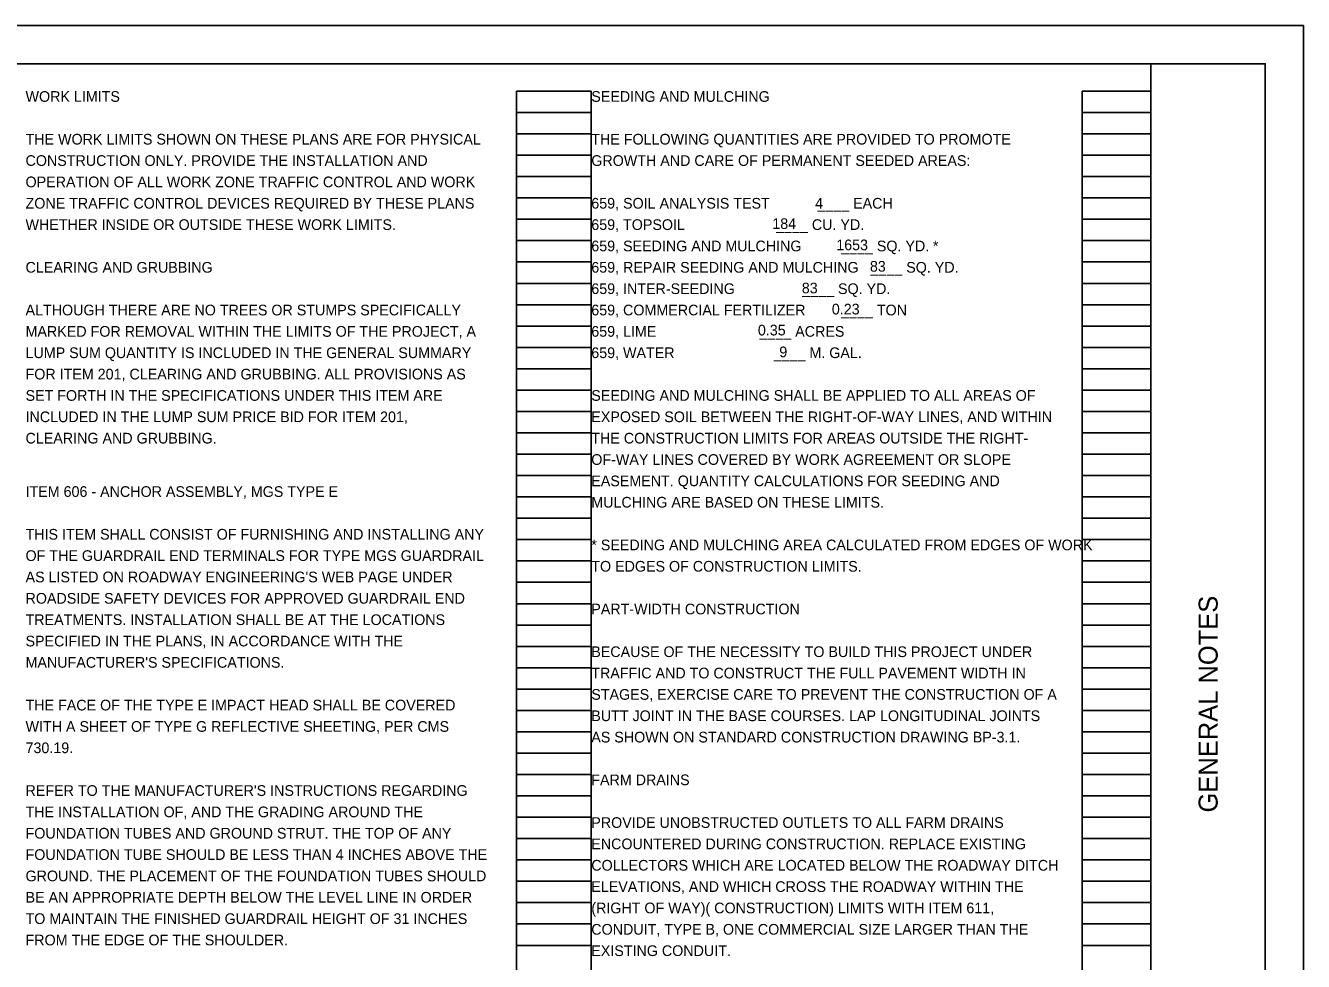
# Model space of a CAD drawing. Extents: x 0 to 37.9, y 0 to 22.
# Drawn here: x 17.24 to 34, y 9.73 to 22 of the extents above; entities that cross this region are included whole.
import ezdxf

# ---------------------------------------------------------------- set-up
doc = ezdxf.new("R2010")
doc.units = 0
for name, color, linetype in [('SH_Border', 7, 'Continuous'), ('SH_Cut_Line', 7, 'Continuous'), ('SH_Data', 7, 'Continuous'), ('SH_Text', 7, 'Continuous')]:
    doc.layers.add(name, color=color, linetype=linetype)

msp = doc.modelspace()

# ---------------------------------------------------------------- linework, layer by layer
at = {"layer": 'SH_Border'}
msp.add_line((32, 0.5), (32, 21.5), dxfattribs=at)
msp.add_lwpolyline([(1.5, 21.5), (33.5, 21.5), (33.5, 0.5), (1.5, 0.5)], close=True, dxfattribs=at)
at = {"layer": 'SH_Cut_Line'}
msp.add_lwpolyline([(0, 0), (34, 0), (34, 22), (0, 22)], close=True, dxfattribs=at)
at = {"layer": 'SH_Data'}
for p, q in [((23.68, 0.98), (23.68, 21.14)), ((23.68, 21.14), (24.66, 21.14)), ((24.66, 0.98), (24.66, 21.14)), ((31.1, 0.98), (31.1, 21.14)), ((31.1, 21.14), (32, 21.14)), ((32, 0.98), (32, 21.14)), ((23.68, 20.86), (24.66, 20.86)), ((31.1, 20.86), (32, 20.86)), ((23.68, 20.58), (24.66, 20.58)), ((31.1, 20.58), (32, 20.58)), ((23.68, 20.3), (24.66, 20.3)), ((31.1, 20.3), (32, 20.3)), ((23.68, 20.02), (24.66, 20.02)), ((31.1, 20.02), (32, 20.02)), ((23.68, 19.74), (24.66, 19.74)), ((31.1, 19.74), (32, 19.74)), ((23.68, 19.46), (24.66, 19.46)), ((31.1, 19.46), (32, 19.46)), ((23.68, 19.18), (24.66, 19.18)), ((31.1, 19.18), (32, 19.18)), ((23.68, 18.9), (24.66, 18.9)), ((31.1, 18.9), (32, 18.9)), ((23.68, 18.62), (24.66, 18.62)), ((31.1, 18.62), (32, 18.62)), ((23.68, 18.34), (24.66, 18.34)), ((31.1, 18.34), (32, 18.34)), ((23.68, 18.06), (24.66, 18.06)), ((31.1, 18.06), (32, 18.06)), ((23.68, 17.78), (24.66, 17.78)), ((31.1, 17.78), (32, 17.78)), ((23.68, 17.5), (24.66, 17.5)), ((31.1, 17.5), (32, 17.5)), ((23.68, 17.22), (24.66, 17.22)), ((31.1, 17.22), (32, 17.22)), ((23.68, 16.94), (24.66, 16.94)), ((31.1, 16.94), (32, 16.94)), ((23.68, 16.66), (24.66, 16.66)), ((31.1, 16.66), (32, 16.66)), ((23.68, 16.38), (24.66, 16.38)), ((31.1, 16.38), (32, 16.38)), ((23.68, 16.1), (24.66, 16.1)), ((31.1, 16.1), (32, 16.1)), ((23.68, 15.82), (24.66, 15.82)), ((31.1, 15.82), (32, 15.82)), ((23.68, 15.54), (24.66, 15.54)), ((31.1, 15.54), (32, 15.54)), ((23.68, 15.26), (24.66, 15.26)), ((31.1, 15.26), (32, 15.26)), ((23.68, 14.98), (24.66, 14.98)), ((31.1, 14.98), (32, 14.98)), ((23.68, 14.7), (24.66, 14.7)), ((31.1, 14.7), (32, 14.7)), ((23.68, 14.42), (24.66, 14.42)), ((31.1, 14.42), (32, 14.42)), ((23.68, 14.14), (24.66, 14.14)), ((31.1, 14.14), (32, 14.14)), ((23.68, 13.86), (24.66, 13.86)), ((31.1, 13.86), (32, 13.86)), ((23.68, 13.58), (24.66, 13.58)), ((31.1, 13.58), (32, 13.58)), ((23.68, 13.3), (24.66, 13.3)), ((31.1, 13.3), (32, 13.3)), ((23.68, 13.02), (24.66, 13.02)), ((31.1, 13.02), (32, 13.02)), ((23.68, 12.74), (24.66, 12.74)), ((31.1, 12.74), (32, 12.74)), ((23.68, 12.46), (24.66, 12.46)), ((31.1, 12.46), (32, 12.46)), ((23.68, 12.18), (24.66, 12.18)), ((31.1, 12.18), (32, 12.18)), ((23.68, 11.9), (24.66, 11.9)), ((31.1, 11.9), (32, 11.9)), ((23.68, 11.62), (24.66, 11.62)), ((31.1, 11.62), (32, 11.62)), ((23.68, 11.34), (24.66, 11.34)), ((31.1, 11.34), (32, 11.34)), ((23.68, 11.06), (24.66, 11.06)), ((31.1, 11.06), (32, 11.06)), ((23.68, 10.78), (24.66, 10.78)), ((31.1, 10.78), (32, 10.78)), ((23.68, 10.5), (24.66, 10.5)), ((31.1, 10.5), (32, 10.5)), ((23.68, 10.22), (24.66, 10.22)), ((31.1, 10.22), (32, 10.22)), ((23.68, 9.94), (24.66, 9.94)), ((31.1, 9.94), (32, 9.94))]:
    msp.add_line(p, q, dxfattribs=at)

# ---------------------------------------------------------------- texts
msp.add_text('GENERAL NOTES', height=0.25, rotation=90, dxfattribs=at).set_placement((32.875, 11.682))
at = {"layer": 'SH_Text'}
for s, p in [('WORK LIMITS', (17.24, 21)), ('SEEDING AND MULCHING', (24.66, 21)), ('THE WORK LIMITS SHOWN ON THESE PLANS ARE FOR PHYSICAL', (17.24, 20.44)), ('THE FOLLOWING QUANTITIES ARE PROVIDED TO PROMOTE', (24.66, 20.44)), ('CONSTRUCTION ONLY. PROVIDE THE INSTALLATION AND', (17.24, 20.16)), ('GROWTH AND CARE OF PERMANENT SEEDED AREAS:', (24.66, 20.16)), ('OPERATION OF ALL WORK ZONE TRAFFIC CONTROL AND WORK', (17.24, 19.88)), ('ZONE TRAFFIC CONTROL DEVICES REQUIRED BY THESE PLANS', (17.24, 19.6)), ('659, SOIL ANALYSIS TEST            ____ EACH', (24.66, 19.6)), ('4', (27.595, 19.6)), ('WHETHER INSIDE OR OUTSIDE THESE WORK LIMITS.', (17.24, 19.32)), ('659, TOPSOIL                       ____ CU. YD.', (24.66, 19.32)), ('184', (27.034, 19.333)), ('659, SEEDING AND MULCHING          ____ SQ. YD.', (24.66, 19.04)), ('1653', (27.873, 19.054)), ('*', (29.14, 19.04)), ('CLEARING AND GRUBBING', (17.24, 18.76)), ('659, REPAIR SEEDING AND MULCHING   ____ SQ. YD.', (24.66, 18.76)), ('83', (28.314, 18.773)), ('659, INTER-SEEDING                 ____ SQ. YD.', (24.66, 18.48)), ('83', (27.421, 18.489)), ('ALTHOUGH THERE ARE NO TREES OR STUMPS SPECIFICALLY', (17.24, 18.2)), ('659, COMMERCIAL FERTILIZER         ____ TON', (24.66, 18.2)), ('0.23', (27.815, 18.212)), ('MARKED FOR REMOVAL WITHIN THE LIMITS OF THE PROJECT, A', (17.24, 17.92)), ('659, LIME                          ____ ACRES', (24.66, 17.92)), ('0.35', (26.845, 17.937)), ('LUMP SUM QUANTITY IS INCLUDED IN THE GENERAL SUMMARY', (17.24, 17.64)), ('659, WATER                         ____ M. GAL.', (24.66, 17.64)), ('9', (27.126, 17.651)), ('FOR ITEM 201, CLEARING AND GRUBBING. ALL PROVISIONS AS', (17.24, 17.36)), ('SET FORTH IN THE SPECIFICATIONS UNDER THIS ITEM ARE', (17.24, 17.08)), ('SEEDING AND MULCHING SHALL BE APPLIED TO ALL AREAS OF', (24.66, 17.08)), ('INCLUDED IN THE LUMP SUM PRICE BID FOR ITEM 201,', (17.24, 16.8)), ('EXPOSED SOIL BETWEEN THE RIGHT-OF-WAY LINES, AND WITHIN', (24.66, 16.8)), ('CLEARING AND GRUBBING.', (17.24, 16.52)), ('THE CONSTRUCTION LIMITS FOR AREAS OUTSIDE THE RIGHT-', (24.66, 16.52)), ('OF-WAY LINES COVERED BY WORK AGREEMENT OR SLOPE', (24.66, 16.24)), ('EASEMENT. QUANTITY CALCULATIONS FOR SEEDING AND', (24.66, 15.96)), ('ITEM 606 - ANCHOR ASSEMBLY, MGS TYPE E', (17.24, 15.82)), ('MULCHING ARE BASED ON THESE LIMITS.', (24.66, 15.68)), ('THIS ITEM SHALL CONSIST OF FURNISHING AND INSTALLING ANY', (17.24, 15.26)), ('* SEEDING AND MULCHING AREA CALCULATED FROM EDGES OF WORK', (24.66, 15.12)), ('OF THE GUARDRAIL END TERMINALS FOR TYPE MGS GUARDRAIL', (17.24, 14.98)), ('TO EDGES OF CONSTRUCTION LIMITS.', (24.66, 14.84)), ("AS LISTED ON ROADWAY ENGINEERING'S WEB PAGE UNDER", (17.24, 14.7)), ('ROADSIDE SAFETY DEVICES FOR APPROVED GUARDRAIL END', (17.24, 14.42)), ('PART-WIDTH CONSTRUCTION', (24.66, 14.28)), ('TREATMENTS. INSTALLATION SHALL BE AT THE LOCATIONS', (17.24, 14.14)), ('SPECIFIED IN THE PLANS, IN ACCORDANCE WITH THE', (17.24, 13.86)), ('BECAUSE OF THE NECESSITY TO BUILD THIS PROJECT UNDER', (24.66, 13.72)), ("MANUFACTURER'S SPECIFICATIONS.", (17.24, 13.58)), ('TRAFFIC AND TO CONSTRUCT THE FULL PAVEMENT WIDTH IN', (24.66, 13.44)), ('STAGES, EXERCISE CARE TO PREVENT THE CONSTRUCTION OF A', (24.66, 13.16)), ('THE FACE OF THE TYPE E IMPACT HEAD SHALL BE COVERED', (17.24, 13.02)), ('BUTT JOINT IN THE BASE COURSES. LAP LONGITUDINAL JOINTS', (24.66, 12.88)), ('WITH A SHEET OF TYPE G REFLECTIVE SHEETING, PER CMS', (17.24, 12.74)), ('AS SHOWN ON STANDARD CONSTRUCTION DRAWING BP-3.1.', (24.66, 12.6)), ('730.19.', (17.24, 12.46)), ('FARM DRAINS', (24.66, 12.04)), ("REFER TO THE MANUFACTURER'S INSTRUCTIONS REGARDING", (17.24, 11.9)), ('THE INSTALLATION OF, AND THE GRADING AROUND THE', (17.24, 11.62)), ('PROVIDE UNOBSTRUCTED OUTLETS TO ALL FARM DRAINS', (24.66, 11.48)), ('FOUNDATION TUBES AND GROUND STRUT. THE TOP OF ANY', (17.24, 11.34)), ('ENCOUNTERED DURING CONSTRUCTION. REPLACE EXISTING', (24.66, 11.2)), ('FOUNDATION TUBE SHOULD BE LESS THAN 4 INCHES ABOVE THE', (17.24, 11.06)), ('COLLECTORS WHICH ARE LOCATED BELOW THE ROADWAY DITCH', (24.66, 10.92)), ('GROUND. THE PLACEMENT OF THE FOUNDATION TUBES SHOULD', (17.24, 10.78)), ('ELEVATIONS, AND WHICH CROSS THE ROADWAY WITHIN THE', (24.66, 10.64)), ('BE AN APPROPRIATE DEPTH BELOW THE LEVEL LINE IN ORDER', (17.24, 10.5)), ('(RIGHT OF WAY)( CONSTRUCTION) LIMITS WITH ITEM 611,', (24.66, 10.36)), ('TO MAINTAIN THE FINISHED GUARDRAIL HEIGHT OF 31 INCHES', (17.24, 10.22)), ('FROM THE EDGE OF THE SHOULDER.', (17.24, 9.94)), ('CONDUIT, TYPE B, ONE COMMERCIAL SIZE LARGER THAN THE', (24.66, 10.08)), ('EXISTING CONDUIT.', (24.66, 9.8))]:
    msp.add_text(s, height=0.14, dxfattribs=at).set_placement(p)

doc.saveas('drawing.dxf')
